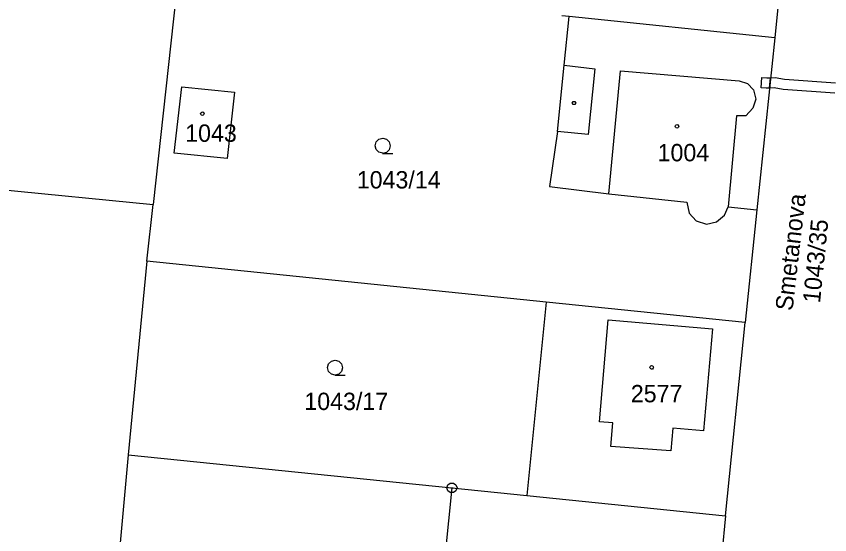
# Model space of a CAD drawing. Extents: x -777309 to -774195, y -1144706 to -1143600.
# Drawn here: x -775252.8 to -775173, y -1144329.3 to -1144278.5 of the extents above; entities that cross this region are included whole.
import ezdxf

# ---------------------------------------------------------------- set-up
doc = ezdxf.new("R2010")
doc.units = 0
for name, color, linetype in [('1', 7, 'Continuous'), ('12', 7, 'Continuous'), ('13', 7, 'Continuous'), ('2', 7, 'Continuous'), ('3', 7, 'Continuous'), ('4', 7, 'Continuous'), ('5', 7, 'Continuous'), ('7', 7, 'Continuous'), ('8', 7, 'Continuous')]:
    doc.layers.add(name, color=color, linetype=linetype)

msp = doc.modelspace()

# ---------------------------------------------------------------- linework, layer by layer
at = {"layer": '1'}
for p, q in [((-775176.38, -1144260.66), (-775178.41, -1144280.62)), ((-775236.87, -1144274.43), (-775239.33, -1144296.93)), ((-775198.56, -1144278.54), (-775199.27, -1144278.47)), ((-775199.05, -1144283.3), (-775198.56, -1144278.54)), ((-775178.41, -1144280.62), (-775198.56, -1144278.54)), ((-775178.41, -1144280.62), (-775180.15, -1144297.46)), ((-775199.71, -1144289.78), (-775199.05, -1144283.3)), ((-775237.28, -1144291.9), (-775236.51, -1144285.43)), ((-775236.51, -1144285.43), (-775231.36, -1144285.93)), ((-775231.36, -1144285.93), (-775232.07, -1144292.44)), ((-775199.71, -1144289.78), (-775200.48, -1144295.17)), ((-775232.07, -1144292.44), (-775237.28, -1144291.9)), ((-775271.6, -1144293.75), (-775239.33, -1144296.93)), ((-775200.48, -1144295.17), (-775194.67, -1144295.88)), ((-775194.67, -1144295.88), (-775187.03, -1144296.72)), ((-775187.03, -1144296.72), (-775186.78, -1144297.78)), ((-775239.94, -1144302.5), (-775239.33, -1144296.93)), ((-775183.33, -1144297.99), (-775182.98, -1144297.17)), ((-775182.98, -1144297.17), (-775180.15, -1144297.46)), ((-775180.15, -1144297.46), (-775181.29, -1144308.5)), ((-775186.78, -1144297.78), (-775186.1, -1144298.53)), ((-775184.13, -1144298.65), (-775183.33, -1144297.99)), ((-775186.1, -1144298.53), (-775185.09, -1144298.85)), ((-775185.09, -1144298.85), (-775184.13, -1144298.65)), ((-775239.94, -1144302.5), (-775241.77, -1144321.45)), ((-775200.81, -1144306.5), (-775239.94, -1144302.5)), ((-775200.81, -1144306.5), (-775202.71, -1144325.45)), ((-775181.29, -1144308.5), (-775200.81, -1144306.5)), ((-775183.24, -1144327.44), (-775181.29, -1144308.5)), ((-775241.77, -1144321.45), (-775242.71, -1144331.45)), ((-775241.77, -1144321.45), (-775210.05, -1144324.7)), ((-775210.05, -1144324.7), (-775212.14, -1144345.14)), ((-775210.05, -1144324.7), (-775202.71, -1144325.45)), ((-775202.71, -1144325.45), (-775183.24, -1144327.44)), ((-775183.24, -1144327.44), (-775185.12, -1144347.36))]:
    msp.add_line(p, q, dxfattribs=at)
at = {"layer": '12'}
for p, q in [((-775194.67, -1144295.88), (-775193.51, -1144283.85)), ((-775193.51, -1144283.85), (-775181.9, -1144284.84)), ((-775237.28, -1144291.9), (-775236.51, -1144285.43)), ((-775236.51, -1144285.43), (-775231.36, -1144285.93)), ((-775181.9, -1144284.84), (-775181.06, -1144285.1)), ((-775181.06, -1144285.1), (-775180.48, -1144285.72)), ((-775231.36, -1144285.93), (-775232.07, -1144292.44)), ((-775180.48, -1144285.72), (-775180.26, -1144286.63)), ((-775180.26, -1144286.63), (-775180.54, -1144287.49)), ((-775180.54, -1144287.49), (-775181.23, -1144288.26)), ((-775182.14, -1144288.26), (-775182.98, -1144297.17)), ((-775181.23, -1144288.26), (-775182.14, -1144288.26)), ((-775232.07, -1144292.44), (-775237.28, -1144291.9)), ((-775194.67, -1144295.88), (-775187.03, -1144296.72)), ((-775187.03, -1144296.72), (-775186.78, -1144297.78)), ((-775183.33, -1144297.99), (-775182.98, -1144297.17)), ((-775186.78, -1144297.78), (-775186.1, -1144298.53)), ((-775184.13, -1144298.65), (-775183.33, -1144297.99)), ((-775186.1, -1144298.53), (-775185.09, -1144298.85)), ((-775185.09, -1144298.85), (-775184.13, -1144298.65)), ((-775195.58, -1144318.22), (-775194.73, -1144308.23)), ((-775194.73, -1144308.23), (-775184.49, -1144309.11)), ((-775184.49, -1144309.11), (-775185.39, -1144319.09)), ((-775194.28, -1144318.33), (-775195.58, -1144318.22)), ((-775194.48, -1144320.63), (-775194.28, -1144318.33)), ((-775188.39, -1144318.83), (-775188.58, -1144321.08)), ((-775185.39, -1144319.09), (-775188.39, -1144318.83)), ((-775188.58, -1144321.08), (-775194.48, -1144320.63))]:
    msp.add_line(p, q, dxfattribs=at)
at = {"layer": '13'}
for p, q in [((-775179.75, -1144285.5), (-775179.67, -1144284.49)), ((-775179.67, -1144284.49), (-775179.17, -1144284.54)), ((-775179.17, -1144284.54), (-775178.81, -1144284.52)), ((-775178.81, -1144284.52), (-775178.92, -1144285.53)), ((-775178.92, -1144285.53), (-775178.81, -1144284.52)), ((-775178.81, -1144284.52), (-775178.37, -1144284.51)), ((-775178.37, -1144284.51), (-775177.45, -1144284.68)), ((-775177.45, -1144284.68), (-775172.45, -1144285.03)), ((-775179.26, -1144285.54), (-775179.75, -1144285.5)), ((-775178.92, -1144285.53), (-775179.26, -1144285.54)), ((-775178.45, -1144285.51), (-775178.92, -1144285.53)), ((-775177.57, -1144285.68), (-775178.45, -1144285.51)), ((-775172.53, -1144286.03), (-775177.57, -1144285.68))]:
    msp.add_line(p, q, dxfattribs=at)
at = {"layer": '3'}
for points in [[(-775216.82, -1144291.92), (-775217.2, -1144291.82), (-775217.47, -1144291.55), (-775217.57, -1144291.18), (-775217.47, -1144290.81), (-775217.2, -1144290.54), (-775216.83, -1144290.44), (-775216.46, -1144290.54), (-775216.19, -1144290.81), (-775216.09, -1144291.19), (-775216.19, -1144291.57), (-775216.46, -1144291.84), (-775216.84, -1144291.94), (-775215.84, -1144291.94)], [(-775221.49, -1144313.65), (-775221.87, -1144313.55), (-775222.14, -1144313.28), (-775222.24, -1144312.91), (-775222.14, -1144312.54), (-775221.87, -1144312.27), (-775221.5, -1144312.17), (-775221.13, -1144312.27), (-775220.86, -1144312.54), (-775220.76, -1144312.92), (-775220.86, -1144313.3), (-775221.13, -1144313.57), (-775221.51, -1144313.67), (-775220.51, -1144313.67)]]:
    msp.add_lwpolyline(points, dxfattribs=at)
at = {"layer": '4'}
for p, q in [((-775199.05, -1144283.3), (-775196.04, -1144283.64)), ((-775196.04, -1144283.64), (-775196.7, -1144290.09)), ((-775194.67, -1144295.88), (-775193.51, -1144283.85)), ((-775193.51, -1144283.85), (-775181.9, -1144284.84)), ((-775181.9, -1144284.84), (-775181.06, -1144285.1)), ((-775181.06, -1144285.1), (-775180.48, -1144285.72)), ((-775180.48, -1144285.72), (-775180.26, -1144286.63)), ((-775180.26, -1144286.63), (-775180.54, -1144287.49)), ((-775180.54, -1144287.49), (-775181.23, -1144288.26)), ((-775182.14, -1144288.26), (-775182.98, -1144297.17)), ((-775181.23, -1144288.26), (-775182.14, -1144288.26)), ((-775196.7, -1144290.09), (-775199.71, -1144289.78)), ((-775195.58, -1144318.22), (-775194.73, -1144308.23)), ((-775194.73, -1144308.23), (-775184.49, -1144309.11)), ((-775184.49, -1144309.11), (-775185.39, -1144319.09)), ((-775194.28, -1144318.33), (-775195.58, -1144318.22)), ((-775194.48, -1144320.63), (-775194.28, -1144318.33)), ((-775188.39, -1144318.83), (-775188.58, -1144321.08)), ((-775185.39, -1144319.09), (-775188.39, -1144318.83)), ((-775188.58, -1144321.08), (-775194.48, -1144320.63))]:
    msp.add_line(p, q, dxfattribs=at)
at = {"layer": '5'}
for points in [[(-775197.99, -1144286.85), (-775197.9, -1144287), (-775197.99, -1144287.15), (-775198.17, -1144287.15), (-775198.26, -1144287), (-775198.17, -1144286.85)], [(-775234.51, -1144287.87), (-775234.41, -1144287.89), (-775234.36, -1144287.98), (-775234.34, -1144288.04), (-775234.36, -1144288.13), (-775234.44, -1144288.2), (-775234.51, -1144288.21), (-775234.6, -1144288.18), (-775234.66, -1144288.12), (-775234.68, -1144288.04), (-775234.66, -1144287.95), (-775234.58, -1144287.88)], [(-775187.99, -1144289.11), (-775187.89, -1144289.13), (-775187.84, -1144289.22), (-775187.82, -1144289.28), (-775187.84, -1144289.37), (-775187.92, -1144289.44), (-775187.99, -1144289.45), (-775188.08, -1144289.42), (-775188.14, -1144289.36), (-775188.16, -1144289.28), (-775188.14, -1144289.19), (-775188.06, -1144289.12)], [(-775190.47, -1144312.72), (-775190.37, -1144312.74), (-775190.32, -1144312.83), (-775190.3, -1144312.89), (-775190.32, -1144312.98), (-775190.4, -1144313.05), (-775190.47, -1144313.06), (-775190.56, -1144313.03), (-775190.62, -1144312.97), (-775190.64, -1144312.89), (-775190.62, -1144312.8), (-775190.54, -1144312.73)]]:
    msp.add_lwpolyline(points, close=True, dxfattribs=at)
at = {"layer": '8'}
msp.add_line((-775210.17, -1144324.7), (-775209.93, -1144324.7), dxfattribs=at)
msp.add_lwpolyline([(-775209.9, -1144324.22), (-775209.65, -1144324.4), (-775209.55, -1144324.69), (-775209.65, -1144324.98), (-775209.9, -1144325.16), (-775210.21, -1144325.16), (-775210.46, -1144324.98), (-775210.56, -1144324.69), (-775210.46, -1144324.4), (-775210.21, -1144324.22)], close=True, dxfattribs=at)

# ---------------------------------------------------------------- texts
at = {"layer": '2'}
for s, p in [('1043', (-775236.197, -1144290.8)), ('1004', (-775189.887, -1144292.71)), ('1043/14', (-775219.377, -1144295.37)), ('2577', (-775192.513, -1144316.31)), ('1043/17', (-775224.517, -1144317.07))]:
    msp.add_text(s, height=1.7, dxfattribs=at).set_placement(p)
msp.add_text('1043/35', height=1.7, rotation=84.2248, dxfattribs=at).set_placement((-775173.97, -1144306.649))
at = {"layer": '7'}
msp.add_text('Smetanova', height=1.7, rotation=83.42265, dxfattribs=at).set_placement((-775176.663, -1144307.404))

doc.saveas('drawing.dxf')
